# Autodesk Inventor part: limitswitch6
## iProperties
Shininess: 0.0
Created: 2002-01
Part Number: limitswitch6
Document SubType Name: Modeling
Density: 1 g/cm^3
Density: 0.0
Volumn: 0.0
Area: 0.0
PropertySet Name: Model Information
Control State: 0
Master: False
Checked Out: False
Author: Administrator
